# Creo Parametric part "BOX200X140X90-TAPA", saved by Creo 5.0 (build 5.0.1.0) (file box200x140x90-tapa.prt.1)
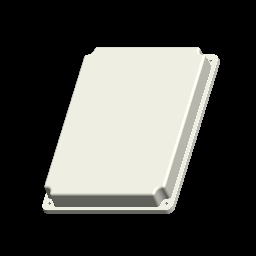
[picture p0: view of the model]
Units: millimeter Kilogram Sec (mmKs); MM, KILOGRAM, SECS
Materials in the file: ABS

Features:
  1. coordinate system "BOX200X140X90-TAPA"
  2. imported feature "Función De Importación ID 5"
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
